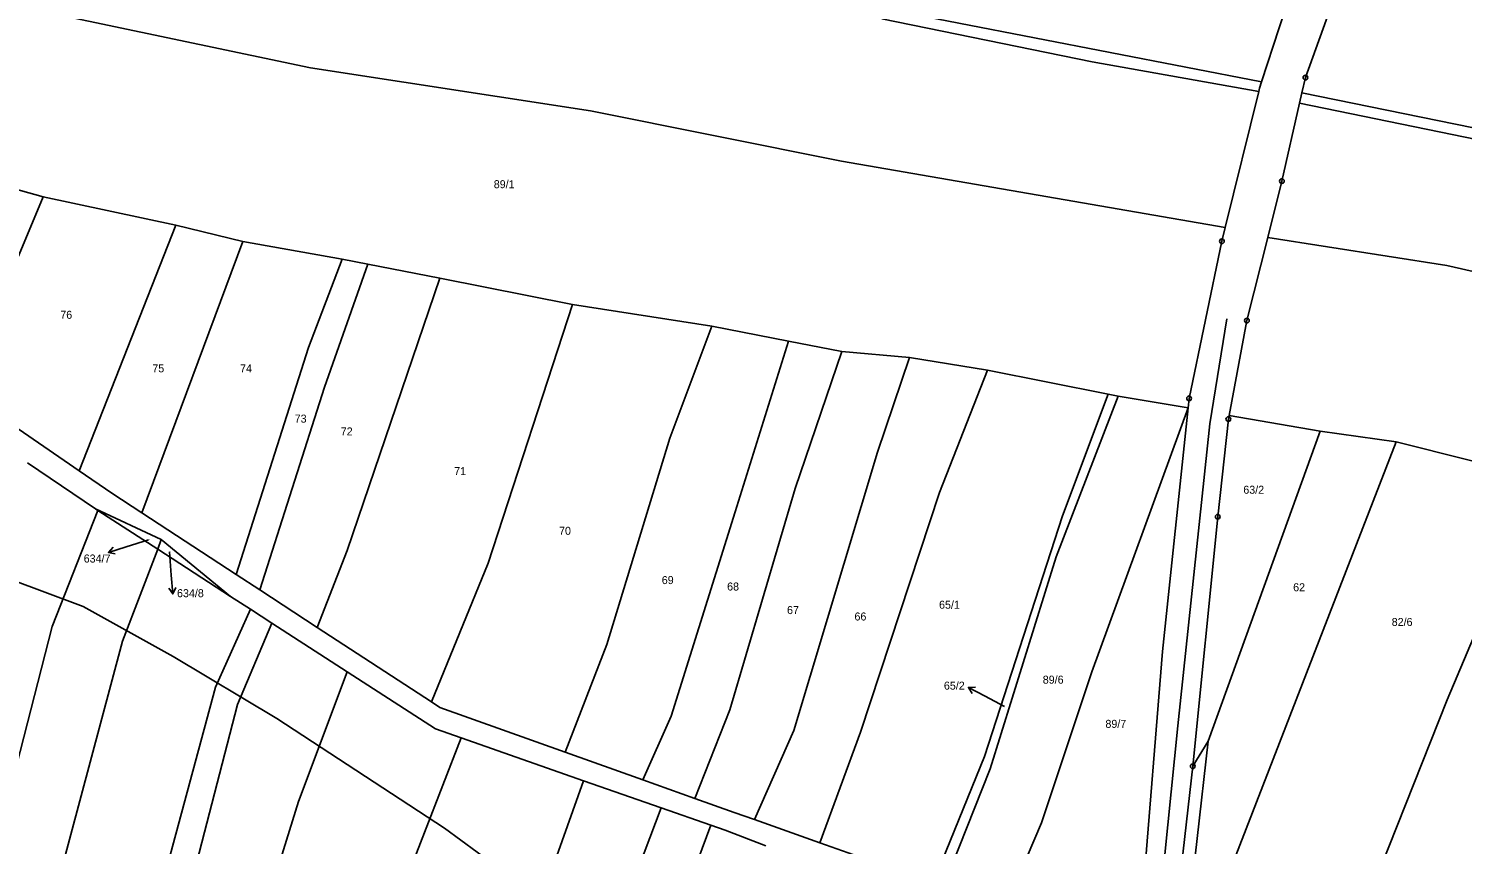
# Model space of a CAD drawing. Extents: x -743888 to -742027, y -1128394 to -1126768.
# Drawn here: x -743566.3 to -743261.6, y -1127493.3 to -1127319.9 of the extents above; entities that cross this region are included whole.
import ezdxf

# ---------------------------------------------------------------- set-up
doc = ezdxf.new("R2010")
doc.units = 0
for name, color, linetype in [('Vrstva 1', 7, 'Continuous'), ('Vrstva 10', 7, 'Continuous'), ('Vrstva 16', 7, 'Continuous'), ('Vrstva 18', 7, 'Continuous'), ('Vrstva 24', 7, 'Continuous'), ('Vrstva 52', 7, 'Continuous'), ('Vrstva 6', 7, 'Continuous')]:
    doc.layers.add(name, color=color, linetype=linetype)

msp = doc.modelspace()

# ---------------------------------------------------------------- linework, layer by layer
at = {"layer": 'Vrstva 1'}
for points in [[(-743304.3, -1127331.19), (-743293.07, -1127296.72)], [(-743294.99, -1127330.28), (-743283.68, -1127298.96)], [(-743304.73, -1127332.52), (-743304.3, -1127331.19)], [(-743295.73, -1127333.53), (-743294.99, -1127330.28)], [(-743312.01, -1127362.15), (-743304.91, -1127333.26)], [(-743304.91, -1127333.26), (-743304.73, -1127332.52)], [(-743296.23, -1127335.74), (-743295.73, -1127333.53)], [(-743299.98, -1127352.31), (-743296.23, -1127335.74)], [(-743302.98, -1127364.26), (-743299.98, -1127352.31)], [(-743312.73, -1127365.1), (-743312.01, -1127362.15)], [(-743307.41, -1127381.95), (-743302.98, -1127364.26)], [(-743319.7, -1127398.48), (-743312.73, -1127365.1)], [(-743311.22, -1127402.11), (-743307.41, -1127381.95)], [(-743580.36, -1127396.81), (-743555.5, -1127413.88)], [(-743325.36, -1127452.28), (-743319.91, -1127400.47)], [(-743319.91, -1127400.47), (-743319.7, -1127398.48)], [(-743313.62, -1127423.64), (-743311.36, -1127402.88)], [(-743311.36, -1127402.88), (-743311.22, -1127402.11)], [(-743566.53, -1127412.16), (-743552.04, -1127421.98)], [(-743555.5, -1127413.88), (-743548.56, -1127418.65)], [(-743548.56, -1127418.65), (-743542.21, -1127422.8)], [(-743552.04, -1127421.98), (-743551.54, -1127422.32)], [(-743551.54, -1127422.32), (-743538.8, -1127430.57)], [(-743542.21, -1127422.8), (-743522.16, -1127435.9)], [(-743318.91, -1127476.67), (-743313.62, -1127423.64)], [(-743538.8, -1127430.57), (-743523.36, -1127440.58)], [(-743522.16, -1127435.9), (-743517.11, -1127439.2)], [(-743523.36, -1127440.58), (-743519.14, -1127443.31)], [(-743517.11, -1127439.2), (-743504.93, -1127447.16)], [(-743519.14, -1127443.31), (-743514.57, -1127446.27)], [(-743514.57, -1127446.27), (-743498.56, -1127456.64)], [(-743504.93, -1127447.16), (-743480.64, -1127463.02)], [(-743329.5, -1127504.03), (-743325.36, -1127452.28)], [(-743498.56, -1127456.64), (-743479.85, -1127468.76)], [(-743480.64, -1127463.02), (-743478.87, -1127464.17)], [(-743478.87, -1127464.17), (-743452.29, -1127473.67)], [(-743479.85, -1127468.76), (-743474.35, -1127470.68)], [(-743474.35, -1127470.68), (-743448.36, -1127479.77)], [(-743452.29, -1127473.67), (-743435.76, -1127479.58)], [(-743323.69, -1127519.01), (-743318.91, -1127476.67)], [(-743448.36, -1127479.77), (-743431.85, -1127485.54)], [(-743435.76, -1127479.58), (-743424.7, -1127483.53)], [(-743424.7, -1127483.53), (-743416.38, -1127486.51)], [(-743431.85, -1127485.54), (-743421.29, -1127489.23)], [(-743416.38, -1127486.51), (-743412.06, -1127488.04)], [(-743421.29, -1127489.23), (-743418.24, -1127490.3)], [(-743412.06, -1127488.04), (-743398.17, -1127492.95)], [(-743418.24, -1127490.3), (-743409.64, -1127493.62)], [(-743398.17, -1127492.95), (-743374.07, -1127501.47)]]:
    msp.add_lwpolyline(points, dxfattribs=at)
at = {"layer": 'Vrstva 10'}
for p, q in [((-743311.69, -1127381.59), (-743315.28, -1127403.91)), ((-743315.28, -1127403.91), (-743322.08, -1127468.07))]:
    msp.add_line(p, q, dxfattribs=at)
msp.add_lwpolyline([(-743322.08, -1127468.07), (-743326.96, -1127516.51)], dxfattribs=at)
at = {"layer": 'Vrstva 16'}
for p, q in [((-743547.87, -1127431.56), (-743549.33, -1127431.22)), ((-743535.02, -1127438.69), (-743535.66, -1127440.05)), ((-743365.79, -1127461.21), (-743366.59, -1127459.94))]:
    msp.add_line(p, q, dxfattribs=at)
for points in [[(-743540.79, -1127428.58), (-743545.51, -1127430.04)], [(-743545.51, -1127430.04), (-743549.33, -1127431.22), (-743548.31, -1127430.12)], [(-743536.35, -1127431.11), (-743535.97, -1127436.06)], [(-743535.97, -1127436.06), (-743535.66, -1127440.05), (-743536.51, -1127438.81)], [(-743363.05, -1127461.8), (-743366.59, -1127459.94), (-743365.09, -1127459.88)], [(-743358.9, -1127463.98), (-743363.05, -1127461.8)]]:
    msp.add_lwpolyline(points, dxfattribs=at)
at = {"layer": 'Vrstva 24'}
for p, q in [((-743295.04, -1127330.28), (-743294.94, -1127330.28)), ((-743300.03, -1127352.31), (-743299.93, -1127352.31)), ((-743312.78, -1127365.1), (-743312.68, -1127365.1)), ((-743307.46, -1127381.95), (-743307.36, -1127381.95)), ((-743319.75, -1127398.48), (-743319.65, -1127398.48)), ((-743311.41, -1127402.88), (-743311.31, -1127402.88)), ((-743313.67, -1127423.64), (-743313.57, -1127423.64)), ((-743318.96, -1127476.67), (-743318.86, -1127476.67))]:
    msp.add_line(p, q, dxfattribs=at)
for centre in [(-743294.99, -1127330.28), (-743299.98, -1127352.31), (-743312.73, -1127365.1), (-743307.41, -1127381.95), (-743319.7, -1127398.48), (-743311.36, -1127402.88), (-743313.62, -1127423.64), (-743318.91, -1127476.67)]:
    msp.add_circle(centre, 0.499, dxfattribs=at)
at = {"layer": 'Vrstva 52'}
for points in [[(-743293.07, -1127296.72), (-743304.3, -1127331.19), (-743304.73, -1127332.52), (-743304.91, -1127333.26), (-743312.01, -1127362.15), (-743312.73, -1127365.1), (-743319.7, -1127398.48), (-743319.91, -1127400.47), (-743325.36, -1127452.28), (-743329.5, -1127504.03), (-743333.57, -1127515.78), (-743331.74, -1127516.48), (-743323.69, -1127519.01), (-743318.91, -1127476.67), (-743313.62, -1127423.64), (-743311.36, -1127402.88), (-743311.22, -1127402.11), (-743307.41, -1127381.95), (-743302.98, -1127364.26), (-743299.98, -1127352.31), (-743296.23, -1127335.74), (-743295.73, -1127333.53), (-743294.99, -1127330.28), (-743283.68, -1127298.96)], [(-743570.38, -1127436.88), (-743554.69, -1127442.75), (-743535.56, -1127453.38), (-743513.5, -1127466.5), (-743477.88, -1127489.88), (-743457.06, -1127505.13), (-743434.19, -1127523), (-743428.69, -1127528), (-743421.44, -1127533.13), (-743407.44, -1127545.88), (-743394.75, -1127561.13), (-743389.19, -1127568.38), (-743379.06, -1127584), (-743372.69, -1127596.75), (-743367.13, -1127612), (-743365.88, -1127617.13), (-743364.19, -1127622.25), (-743358.25, -1127652.75), (-743358.25, -1127657.88), (-743357, -1127680.75)]]:
    msp.add_lwpolyline(points, dxfattribs=at)
at = {"layer": 'Vrstva 6'}
for points in [[(-743432.95, -1127306.22), (-743304.3, -1127331.19)], [(-743565.99, -1127315.69), (-743506.37, -1127328.2)], [(-743384.95, -1127317.8), (-743340.32, -1127326.98)], [(-743506.37, -1127328.2), (-743446.91, -1127337.38)], [(-743340.32, -1127326.98), (-743304.91, -1127333.26)], [(-743295.73, -1127333.53), (-743237.76, -1127345.4)], [(-743446.91, -1127337.38), (-743393.56, -1127348.06)], [(-743296.23, -1127335.74), (-743196.16, -1127356.25)], [(-743393.56, -1127348.06), (-743312.01, -1127362.15)], [(-743578.94, -1127351.24), (-743563.19, -1127355.67)], [(-743580.36, -1127396.81), (-743563.19, -1127355.67)], [(-743563.19, -1127355.67), (-743534.99, -1127361.65)], [(-743555.5, -1127413.88), (-743534.99, -1127361.65)], [(-743534.99, -1127361.65), (-743520.78, -1127365.13)], [(-743302.98, -1127364.26), (-743264.92, -1127370.24)], [(-743542.21, -1127422.8), (-743520.78, -1127365.13)], [(-743520.78, -1127365.13), (-743499.65, -1127368.91)], [(-743506.82, -1127387.68), (-743499.65, -1127368.91)], [(-743503.41, -1127396.1), (-743494.17, -1127369.95)], [(-743499.65, -1127368.91), (-743494.17, -1127369.95)], [(-743494.17, -1127369.95), (-743478.91, -1127372.96)], [(-743264.92, -1127370.24), (-743199.65, -1127385.13)], [(-743498.61, -1127430.83), (-743478.91, -1127372.96)], [(-743478.91, -1127372.96), (-743450.74, -1127378.54)], [(-743468.63, -1127433.52), (-743450.74, -1127378.54)], [(-743450.74, -1127378.54), (-743421.13, -1127383.11)], [(-743430.01, -1127406.91), (-743421.13, -1127383.11)], [(-743421.13, -1127383.11), (-743404.84, -1127386.3)], [(-743522.16, -1127435.9), (-743506.82, -1127387.68)], [(-743416.15, -1127422.6), (-743404.84, -1127386.3)], [(-743404.84, -1127386.3), (-743393.46, -1127388.49)], [(-743403.43, -1127417.65), (-743393.46, -1127388.49)], [(-743393.46, -1127388.49), (-743379.14, -1127389.77)], [(-743385.89, -1127409.89), (-743379.14, -1127389.77)], [(-743379.14, -1127389.77), (-743362.5, -1127392.49)], [(-743372.73, -1127418.53), (-743362.5, -1127392.49)], [(-743362.5, -1127392.49), (-743336.87, -1127397.58)], [(-743517.11, -1127439.2), (-743503.41, -1127396.1)], [(-743347.91, -1127432.2), (-743334.8, -1127397.99)], [(-743346.61, -1127423.47), (-743336.87, -1127397.58)], [(-743336.87, -1127397.58), (-743334.8, -1127397.99)], [(-743334.8, -1127397.99), (-743319.91, -1127400.47)], [(-743340.35, -1127456.63), (-743319.91, -1127400.47)], [(-743311.22, -1127402.11), (-743291.86, -1127405.49)], [(-743443.41, -1127450.8), (-743430.01, -1127406.91)], [(-743315.66, -1127471.33), (-743291.86, -1127405.49)], [(-743291.86, -1127405.49), (-743275.71, -1127407.69)], [(-743403.69, -1127469.09), (-743385.89, -1127409.89)], [(-743311.15, -1127499.13), (-743275.71, -1127407.69)], [(-743275.71, -1127407.69), (-743244.94, -1127415.47)], [(-743264.86, -1127462.59), (-743244.94, -1127415.47)], [(-743417.28, -1127464.67), (-743403.43, -1127417.65)], [(-743389.53, -1127469.42), (-743372.73, -1127418.53)], [(-743561.28, -1127447), (-743551.54, -1127422.32)], [(-743552.04, -1127421.98), (-743538.08, -1127428.5)], [(-743429.78, -1127466.03), (-743416.15, -1127422.6)], [(-743363.18, -1127474.59), (-743346.61, -1127423.47)], [(-743538.8, -1127430.57), (-743538.08, -1127428.5)], [(-743538.08, -1127428.5), (-743523.36, -1127440.58)], [(-743546.31, -1127450.09), (-743538.8, -1127430.57)], [(-743504.93, -1127447.16), (-743498.61, -1127430.83)], [(-743480.64, -1127463.02), (-743468.63, -1127433.52)], [(-743362, -1127477.23), (-743347.91, -1127432.2)], [(-743526.58, -1127459.91), (-743519.14, -1127443.31)], [(-743590.72, -1127561.84), (-743561.28, -1127447)], [(-743521.89, -1127463.56), (-743514.57, -1127446.27)], [(-743579.58, -1127574.43), (-743546.31, -1127450.09)], [(-743452.29, -1127473.67), (-743443.41, -1127450.8)], [(-743508.94, -1127484.15), (-743498.56, -1127456.64)], [(-743351.05, -1127488.73), (-743340.35, -1127456.63)], [(-743554.73, -1127564.38), (-743526.58, -1127459.91)], [(-743545.21, -1127553.77), (-743521.89, -1127463.56)], [(-743424.7, -1127483.53), (-743417.28, -1127464.67)], [(-743284.35, -1127511.68), (-743264.86, -1127462.59)], [(-743435.76, -1127479.58), (-743429.78, -1127466.03)], [(-743486.04, -1127500.8), (-743474.35, -1127470.68)], [(-743412.06, -1127488.04), (-743403.69, -1127469.09)], [(-743398.17, -1127492.95), (-743389.53, -1127469.42)], [(-743320.31, -1127512.72), (-743315.66, -1127471.33)], [(-743318.91, -1127476.67), (-743315.66, -1127471.33)], [(-743374.07, -1127501.47), (-743363.18, -1127474.59)], [(-743371.91, -1127502.23), (-743362, -1127477.23)], [(-743455.14, -1127498.91), (-743448.36, -1127479.77)], [(-743529.52, -1127550.64), (-743508.94, -1127484.15)], [(-743442.53, -1127513.63), (-743431.85, -1127485.54)], [(-743434.5, -1127524.7), (-743421.29, -1127489.23)], [(-743358.75, -1127506.88), (-743351.05, -1127488.73)]]:
    msp.add_lwpolyline(points, dxfattribs=at)

# ---------------------------------------------------------------- texts
at = {"layer": 'Vrstva 16'}
for s, p in [('634/7', (-743554.57, -1127433.38)), ('634/8', (-743534.74, -1127440.75)), ('65/2', (-743371.8, -1127460.4))]:
    msp.add_text(s, height=1.7, dxfattribs=at).set_placement(p)
at = {"layer": 'Vrstva 18'}
for s, height, p in [('89/1', 1.7, (-743467.44, -1127353.81)), ('76', 1.7, (-743559.54, -1127381.57)), ('75', 1.7, (-743539.99, -1127392.95)), ('74', 1.7, (-743521.34, -1127392.95)), ('73', 1.7, (-743509.74, -1127403.64)), ('72', 1.7, (-743499.96, -1127406.37)), ('71', 1.7, (-743475.85, -1127414.79)), ('63/2', 1.7, (-743308.18, -1127418.76)), ('70', 1.7, (-743453.57, -1127427.49)), ('634/7', 0.1, (-743540.79, -1127428.58)), ('634/8', 0.1, (-743536.35, -1127431.11)), ('69', 1.7, (-743431.74, -1127437.96)), ('68', 1.7, (-743417.86, -1127439.33)), ('62', 1.7, (-743297.59, -1127439.49)), ('67', 1.7, (-743405.13, -1127444.34)), ('66', 1.7, (-743390.8, -1127445.7)), ('65/1', 1.7, (-743372.83, -1127443.2)), ('82/6', 1.7, (-743276.65, -1127446.86)), ('89/6', 1.7, (-743350.79, -1127459.13)), ('65/2', 0.1, (-743358.9, -1127463.98)), ('89/7', 1.7, (-743337.48, -1127468.52))]:
    msp.add_text(s, height=height, dxfattribs=at).set_placement(p)

doc.saveas('drawing.dxf')
